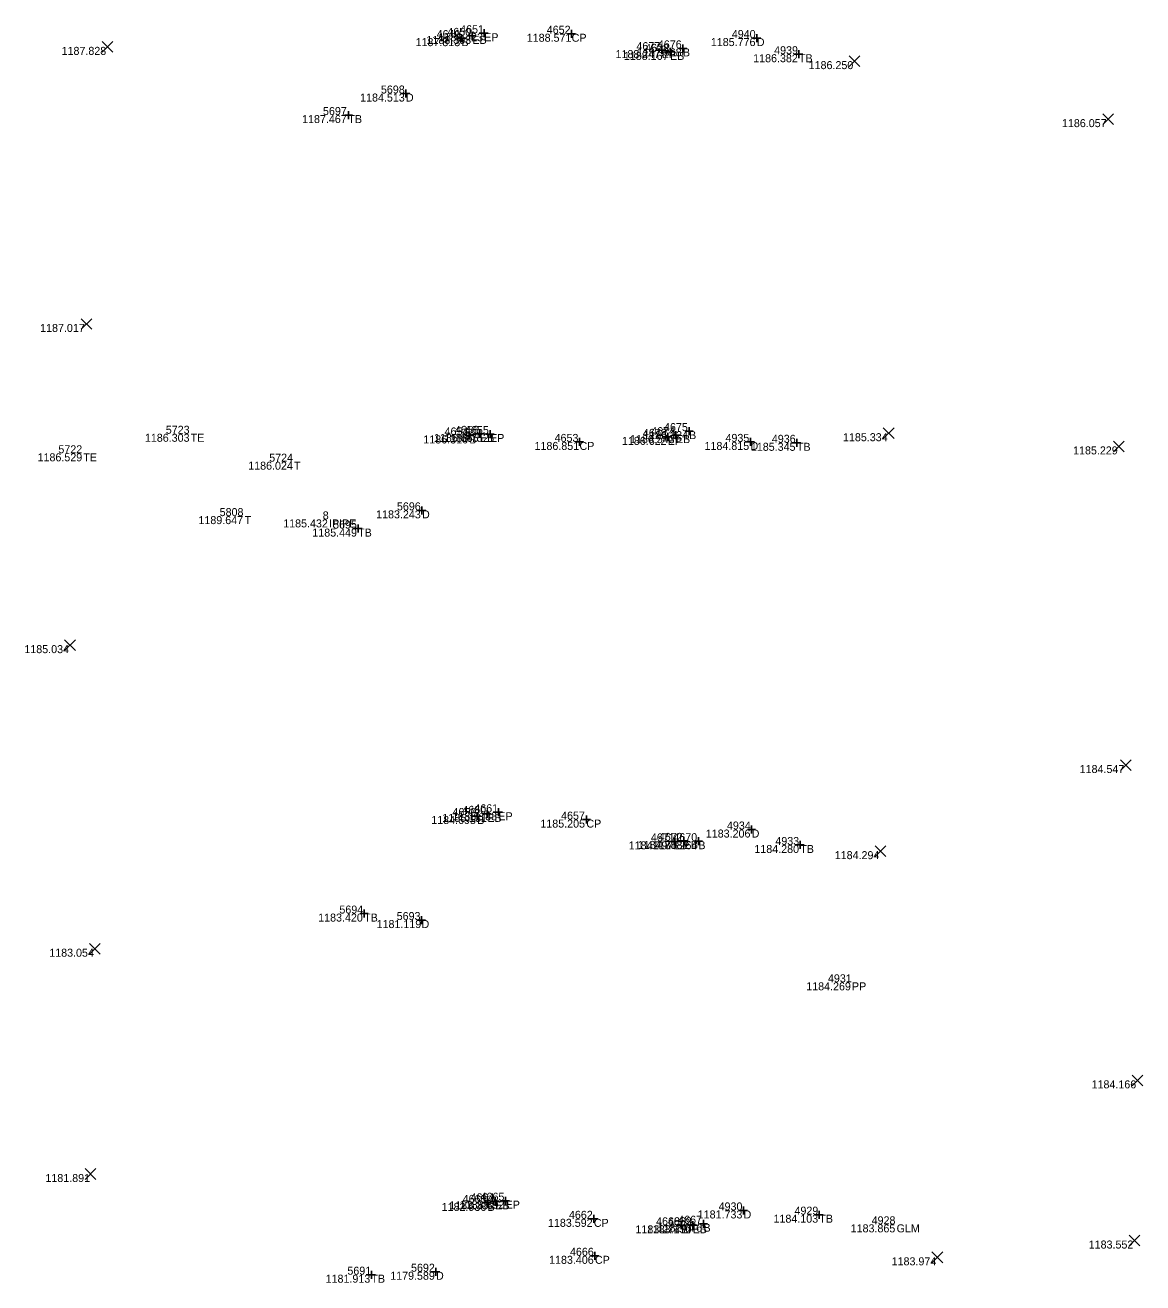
# Model space of a CAD drawing. Extents: x 2044997 to 2050342, y 455233 to 458054.
# Drawn here: x 2047582.6 to 2047722.3, y 455973.2 to 456130.3 of the extents above; entities that cross this region are included whole.
import ezdxf

# ---------------------------------------------------------------- set-up
doc = ezdxf.new("R2010")
doc.units = 0
for name, color, linetype in [('SV_X_Random_Point', 7, 'Continuous'), ('SV_X_Shot_Marker', 7, 'Continuous'), ('SV_X_Text_Comment', 7, 'Continuous'), ('SV_X_Text_Elevation', 7, 'Continuous'), ('SV_X_Text_Name', 7, 'Continuous')]:
    doc.layers.add(name, color=color, linetype=linetype)

msp = doc.modelspace()

# ---------------------------------------------------------------- linework, layer by layer
at = {"layer": 'SV_X_Random_Point'}
for p, q in [((2047592.23, 456126.95), (2047593.56, 456128.29)), ((2047592.23, 456128.29), (2047593.56, 456126.95)), ((2047685.57, 456125.17), (2047686.9, 456126.5)), ((2047685.57, 456126.5), (2047686.9, 456125.17)), ((2047717.26, 456117.92), (2047718.59, 456119.25)), ((2047717.26, 456119.25), (2047718.59, 456117.92)), ((2047589.59, 456092.33), (2047590.93, 456093.66)), ((2047589.59, 456093.66), (2047590.93, 456092.33)), ((2047689.83, 456078.68), (2047691.17, 456080.02)), ((2047689.83, 456080.02), (2047691.17, 456078.68)), ((2047718.59, 456077.04), (2047719.92, 456078.37)), ((2047718.59, 456078.37), (2047719.92, 456077.04)), ((2047587.54, 456052.21), (2047588.88, 456053.54)), ((2047587.54, 456053.54), (2047588.88, 456052.21)), ((2047719.47, 456037.22), (2047720.81, 456038.56)), ((2047719.47, 456038.56), (2047720.81, 456037.22)), ((2047688.8, 456026.46), (2047690.13, 456027.8)), ((2047688.8, 456027.8), (2047690.13, 456026.46)), ((2047590.66, 456014.27), (2047591.99, 456015.61)), ((2047590.66, 456015.61), (2047591.99, 456014.27)), ((2047720.92, 455997.82), (2047722.25, 455999.16)), ((2047720.92, 455999.16), (2047722.25, 455997.82)), ((2047590.09, 455986.12), (2047591.42, 455987.46)), ((2047590.09, 455987.46), (2047591.42, 455986.12)), ((2047720.55, 455977.81), (2047721.89, 455979.14)), ((2047720.55, 455979.14), (2047721.89, 455977.81)), ((2047695.91, 455975.71), (2047697.25, 455977.05)), ((2047695.91, 455977.05), (2047697.25, 455975.71))]:
    msp.add_line(p, q, dxfattribs=at)
at = {"layer": 'SV_X_Shot_Marker'}
for p, q in [((2047637.12, 456129.21), (2047637.12, 456128.21)), ((2047638.48, 456129.49), (2047638.48, 456128.49)), ((2047639.46, 456129.32), (2047640.46, 456129.32)), ((2047639.96, 456129.82), (2047639.96, 456128.82)), ((2047639.96, 456129.32), (2047639.96, 456129.32)), ((2047650.39, 456129.26), (2047651.39, 456129.26)), ((2047650.89, 456129.76), (2047650.89, 456128.76)), ((2047650.89, 456129.26), (2047650.89, 456129.26)), ((2047674.02, 456129.22), (2047674.02, 456128.22)), ((2047636.62, 456128.71), (2047637.62, 456128.71)), ((2047637.12, 456128.71), (2047637.12, 456128.71)), ((2047637.98, 456128.99), (2047638.98, 456128.99)), ((2047638.48, 456128.99), (2047638.48, 456128.99)), ((2047662.14, 456127.71), (2047662.14, 456126.71)), ((2047664.79, 456127.93), (2047664.79, 456126.93)), ((2047673.52, 456128.72), (2047674.52, 456128.72)), ((2047674.02, 456128.72), (2047674.02, 456128.72)), ((2047661.64, 456127.21), (2047662.64, 456127.21)), ((2047662.14, 456127.21), (2047662.14, 456127.21)), ((2047662.69, 456126.99), (2047663.69, 456126.99)), ((2047663.19, 456127.49), (2047663.19, 456126.49)), ((2047663.19, 456126.99), (2047663.19, 456126.99)), ((2047664.29, 456127.43), (2047665.29, 456127.43)), ((2047664.79, 456127.43), (2047664.79, 456127.43)), ((2047678.79, 456126.7), (2047679.79, 456126.7)), ((2047679.29, 456127.2), (2047679.29, 456126.2)), ((2047679.29, 456126.7), (2047679.29, 456126.7)), ((2047629.68, 456121.79), (2047630.68, 456121.79)), ((2047630.18, 456122.29), (2047630.18, 456121.29)), ((2047630.18, 456121.79), (2047630.18, 456121.79)), ((2047622.49, 456119.1), (2047623.49, 456119.1)), ((2047622.99, 456119.6), (2047622.99, 456118.6)), ((2047622.99, 456119.1), (2047622.99, 456119.1)), ((2047637.6, 456079.07), (2047638.6, 456079.07)), ((2047638.1, 456079.57), (2047638.1, 456078.57)), ((2047638.1, 456079.07), (2047638.1, 456079.07)), ((2047638.93, 456079.27), (2047639.93, 456079.27)), ((2047639.43, 456079.77), (2047639.43, 456078.77)), ((2047639.43, 456079.27), (2047639.43, 456079.27)), ((2047640.2, 456079.25), (2047641.2, 456079.25)), ((2047640.7, 456079.75), (2047640.7, 456078.75)), ((2047640.7, 456079.25), (2047640.7, 456079.25)), ((2047662.4, 456078.89), (2047663.4, 456078.89)), ((2047662.9, 456079.39), (2047662.9, 456078.39)), ((2047662.9, 456078.89), (2047662.9, 456078.89)), ((2047663.41, 456079.11), (2047664.41, 456079.11)), ((2047663.91, 456079.61), (2047663.91, 456078.61)), ((2047663.91, 456079.11), (2047663.91, 456079.11)), ((2047665.06, 456079.61), (2047666.06, 456079.61)), ((2047665.56, 456080.11), (2047665.56, 456079.11)), ((2047665.56, 456079.61), (2047665.56, 456079.61)), ((2047651.37, 456078.26), (2047652.37, 456078.26)), ((2047651.87, 456078.76), (2047651.87, 456077.76)), ((2047651.87, 456078.26), (2047651.87, 456078.26)), ((2047672.74, 456078.26), (2047673.74, 456078.26)), ((2047673.24, 456078.76), (2047673.24, 456077.76)), ((2047673.24, 456078.26), (2047673.24, 456078.26)), ((2047678.53, 456078.15), (2047679.53, 456078.15)), ((2047679.03, 456078.65), (2047679.03, 456077.65)), ((2047679.03, 456078.15), (2047679.03, 456078.15)), ((2047631.69, 456069.71), (2047632.69, 456069.71)), ((2047632.19, 456070.21), (2047632.19, 456069.21)), ((2047632.19, 456069.71), (2047632.19, 456069.71)), ((2047624.21, 456067.93), (2047624.21, 456066.93)), ((2047623.71, 456067.43), (2047624.71, 456067.43)), ((2047624.21, 456067.43), (2047624.21, 456067.43)), ((2047639.09, 456032.02), (2047639.09, 456031.02)), ((2047639.85, 456031.79), (2047640.85, 456031.79)), ((2047640.35, 456032.29), (2047640.35, 456031.29)), ((2047640.35, 456031.79), (2047640.35, 456031.79)), ((2047641.23, 456031.99), (2047642.23, 456031.99)), ((2047641.73, 456032.49), (2047641.73, 456031.49)), ((2047641.73, 456031.99), (2047641.73, 456031.99)), ((2047638.59, 456031.52), (2047639.59, 456031.52)), ((2047639.09, 456031.52), (2047639.09, 456031.52)), ((2047652.23, 456031.07), (2047653.23, 456031.07)), ((2047652.73, 456031.57), (2047652.73, 456030.57)), ((2047652.73, 456031.07), (2047652.73, 456031.07)), ((2047673.38, 456030.33), (2047673.38, 456029.33)), ((2047663.79, 456028.85), (2047663.79, 456027.85)), ((2047664.9, 456028.91), (2047664.9, 456027.91)), ((2047666.72, 456028.87), (2047666.72, 456027.87)), ((2047672.88, 456029.83), (2047673.88, 456029.83)), ((2047673.38, 456029.83), (2047673.38, 456029.83)), ((2047663.29, 456028.35), (2047664.29, 456028.35)), ((2047663.79, 456028.35), (2047663.79, 456028.35)), ((2047664.4, 456028.41), (2047665.4, 456028.41)), ((2047664.9, 456028.41), (2047664.9, 456028.41)), ((2047666.22, 456028.37), (2047667.22, 456028.37)), ((2047666.72, 456028.37), (2047666.72, 456028.37)), ((2047678.95, 456027.9), (2047679.95, 456027.9)), ((2047679.45, 456028.4), (2047679.45, 456027.4)), ((2047679.45, 456027.9), (2047679.45, 456027.9)), ((2047624.46, 456019.33), (2047625.46, 456019.33)), ((2047624.96, 456019.83), (2047624.96, 456018.83)), ((2047624.96, 456019.33), (2047624.96, 456019.33)), ((2047631.63, 456018.52), (2047632.63, 456018.52)), ((2047632.13, 456019.02), (2047632.13, 456018.02)), ((2047632.13, 456018.52), (2047632.13, 456018.52)), ((2047639.88, 455983.18), (2047640.88, 455983.18)), ((2047640.38, 455983.68), (2047640.38, 455982.68)), ((2047640.38, 455983.18), (2047640.38, 455983.18)), ((2047640.84, 455983.38), (2047641.84, 455983.38)), ((2047641.34, 455983.88), (2047641.34, 455982.88)), ((2047641.34, 455983.38), (2047641.34, 455983.38)), ((2047642.14, 455983.46), (2047643.14, 455983.46)), ((2047642.64, 455983.96), (2047642.64, 455982.96)), ((2047642.64, 455983.46), (2047642.64, 455983.46)), ((2047653.66, 455981.69), (2047653.66, 455980.69)), ((2047671.87, 455982.24), (2047672.87, 455982.24)), ((2047672.37, 455982.74), (2047672.37, 455981.74)), ((2047672.37, 455982.24), (2047672.37, 455982.24)), ((2047681.33, 455981.71), (2047682.33, 455981.71)), ((2047681.83, 455982.21), (2047681.83, 455981.21)), ((2047681.83, 455981.71), (2047681.83, 455981.71)), ((2047653.16, 455981.19), (2047654.16, 455981.19)), ((2047653.66, 455981.19), (2047653.66, 455981.19)), ((2047664.06, 455980.38), (2047665.06, 455980.38)), ((2047664.56, 455980.88), (2047664.56, 455979.88)), ((2047664.56, 455980.38), (2047664.56, 455980.38)), ((2047665.51, 455980.39), (2047666.51, 455980.39)), ((2047666.01, 455980.89), (2047666.01, 455979.89)), ((2047666.01, 455980.39), (2047666.01, 455980.39)), ((2047666.86, 455980.58), (2047667.86, 455980.58)), ((2047667.36, 455981.08), (2047667.36, 455980.08)), ((2047667.36, 455980.58), (2047667.36, 455980.58)), ((2047653.8, 455977.07), (2047653.8, 455976.07)), ((2047653.3, 455976.57), (2047654.3, 455976.57)), ((2047653.8, 455976.57), (2047653.8, 455976.57)), ((2047625.37, 455974.21), (2047626.37, 455974.21)), ((2047625.87, 455974.71), (2047625.87, 455973.71)), ((2047625.87, 455974.21), (2047625.87, 455974.21)), ((2047633.44, 455974.58), (2047634.44, 455974.58)), ((2047633.94, 455975.08), (2047633.94, 455974.08)), ((2047633.94, 455974.58), (2047633.94, 455974.58))]:
    msp.add_line(p, q, dxfattribs=at)

# ---------------------------------------------------------------- texts
at = {"layer": 'SV_X_Text_Comment'}
for s, p in [('EP', (2047639.96, 456128.32)), ('CP', (2047650.89, 456128.26)), ('B', (2047637.12, 456127.71)), ('EB', (2047638.48, 456127.99)), ('D', (2047674.02, 456127.72)), ('EP', (2047662.14, 456126.21)), ('EB', (2047663.19, 456125.99)), ('B', (2047664.79, 456126.43)), ('TB', (2047679.29, 456125.7)), ('D', (2047630.18, 456120.79)), ('TB', (2047622.99, 456118.1)), ('TE', (2047603.29, 456078.28)), ('B', (2047638.1, 456078.07)), ('EB', (2047639.43, 456078.27)), ('EP', (2047640.7, 456078.25)), ('EP', (2047662.9, 456077.89)), ('EB', (2047663.91, 456078.11)), ('B', (2047665.56, 456078.61)), ('CP', (2047651.87, 456077.26)), ('D', (2047673.24, 456077.26)), ('TB', (2047679.03, 456077.15)), ('TE', (2047589.87, 456075.84)), ('T', (2047616.19, 456074.79)), ('D', (2047632.19, 456068.71)), ('T', (2047610.03, 456067.99)), ('IPIPE', (2047620.58, 456067.58)), ('TB', (2047624.21, 456066.43)), ('EB', (2047640.35, 456030.79)), ('EP', (2047641.73, 456030.99)), ('B', (2047639.09, 456030.52)), ('CP', (2047652.73, 456030.07)), ('D', (2047673.38, 456028.83)), ('EP', (2047663.79, 456027.35)), ('EB', (2047664.9, 456027.41)), ('B', (2047666.72, 456027.37)), ('TB', (2047679.45, 456026.9)), ('TB', (2047624.96, 456018.33)), ('D', (2047632.13, 456017.52)), ('PP', (2047685.91, 456009.74)), ('B', (2047640.38, 455982.18)), ('EB', (2047641.34, 455982.38)), ('EP', (2047642.64, 455982.46)), ('D', (2047672.37, 455981.24)), ('TB', (2047681.83, 455980.71)), ('CP', (2047653.66, 455980.19)), ('EP', (2047664.56, 455979.38)), ('EB', (2047666.01, 455979.39)), ('B', (2047667.36, 455979.58)), ('GLM', (2047691.49, 455979.5)), ('CP', (2047653.8, 455975.57)), ('TB', (2047625.87, 455973.21)), ('D', (2047633.94, 455973.58))]:
    msp.add_text(s, height=1, dxfattribs=at).set_placement(p)
at = {"layer": 'SV_X_Text_Elevation'}
for s, p in [('1188.423', (2047634.24, 456128.32)), ('1188.571', (2047645.28, 456128.26)), ('1187.828', (2047587.16, 456126.62)), ('1187.813', (2047631.39, 456127.71)), ('1188.303', (2047632.75, 456127.99)), ('1185.776', (2047668.28, 456127.72)), ('1188.247', (2047656.37, 456126.21)), ('1188.167', (2047657.41, 456125.99)), ('1187.968', (2047659.05, 456126.43)), ('1186.382', (2047673.57, 456125.7)), ('1186.250', (2047680.5, 456124.84)), ('1184.513', (2047624.46, 456120.79)), ('1187.467', (2047617.21, 456118.1)), ('1186.057', (2047712.15, 456117.59)), ('1187.017', (2047584.48, 456092)), ('1186.303', (2047597.57, 456078.28)), ('1186.316', (2047632.36, 456078.07)), ('1186.665', (2047633.68, 456078.27)), ('1186.752', (2047634.97, 456078.25)), ('1186.622', (2047657.17, 456077.89)), ('1186.543', (2047658.18, 456078.11)), ('1186.324', (2047659.85, 456078.61)), ('1185.334', (2047684.79, 456078.35)), ('1186.851', (2047646.25, 456077.26)), ('1184.815', (2047667.49, 456077.26)), ('1185.345', (2047673.28, 456077.15)), ('1185.229', (2047713.54, 456076.7)), ('1186.529', (2047584.16, 456075.84)), ('1186.024', (2047610.48, 456074.79)), ('1183.243', (2047626.46, 456068.71)), ('1189.647', (2047604.26, 456067.99)), ('1185.432', (2047614.85, 456067.58)), ('1185.449', (2047618.49, 456066.43)), ('1185.034', (2047582.51, 456051.87)), ('1184.547', (2047714.36, 456036.89)), ('1185.131', (2047634.73, 456030.79)), ('1185.188', (2047635.99, 456030.99)), ('1184.695', (2047633.35, 456030.52)), ('1185.205', (2047646.98, 456030.07)), ('1183.206', (2047667.65, 456028.83)), ('1184.797', (2047658.02, 456027.35)), ('1184.738', (2047659.16, 456027.41)), ('1184.264', (2047661.02, 456027.37)), ('1184.280', (2047673.72, 456026.9)), ('1184.294', (2047683.76, 456026.13)), ('1183.420', (2047619.22, 456018.33)), ('1181.119', (2047626.52, 456017.52)), ('1183.054', (2047585.62, 456013.94)), ('1184.269', (2047680.2, 456009.74)), ('1184.166', (2047715.85, 455997.49)), ('1181.891', (2047585.14, 455985.79)), ('1182.936', (2047634.65, 455982.18)), ('1183.330', (2047635.6, 455982.38)), ('1183.392', (2047636.91, 455982.46)), ('1181.733', (2047666.64, 455981.24)), ('1184.103', (2047676.11, 455980.71)), ('1183.592', (2047647.93, 455980.19)), ('1183.274', (2047658.86, 455979.38)), ('1183.130', (2047660.28, 455979.39)), ('1182.676', (2047661.62, 455979.58)), ('1183.865', (2047685.75, 455979.5)), ('1183.552', (2047715.49, 455977.48)), ('1183.406', (2047648.07, 455975.57)), ('1183.974', (2047690.87, 455975.38)), ('1181.913', (2047620.15, 455973.21)), ('1179.589', (2047628.22, 455973.58))]:
    msp.add_text(s, height=1, dxfattribs=at).set_placement(p)
at = {"layer": 'SV_X_Text_Name'}
for s, p in [('4649', (2047634.02, 456128.71)), ('4650', (2047635.36, 456128.99)), ('4651', (2047636.96, 456129.32)), ('4652', (2047647.78, 456129.26)), ('4940', (2047670.9, 456128.72)), ('4677', (2047658.98, 456127.21)), ('4678', (2047660.07, 456126.99)), ('4676', (2047661.66, 456127.43)), ('4939', (2047676.19, 456126.7)), ('5698', (2047627.06, 456121.79)), ('5697', (2047619.82, 456119.1)), ('4675', (2047662.43, 456079.61)), ('5723', (2047600.18, 456079.28)), ('4654', (2047635.01, 456079.07)), ('4656', (2047636.3, 456079.27)), ('4655', (2047637.57, 456079.25)), ('4653', (2047648.76, 456078.26)), ('4673', (2047659.79, 456078.89)), ('4674', (2047660.82, 456079.11)), ('4935', (2047670.11, 456078.26)), ('4936', (2047675.9, 456078.15)), ('5722', (2047586.76, 456076.84)), ('5724', (2047613.1, 456075.79)), ('5808', (2047606.91, 456068.99)), ('8', (2047619.79, 456068.58)), ('5696', (2047629.06, 456069.71)), ('5695', (2047621.08, 456067.43)), ('4659', (2047635.99, 456031.52)), ('4660', (2047637.23, 456031.79)), ('4661', (2047638.73, 456031.99)), ('4657', (2047649.57, 456031.07)), ('4934', (2047670.29, 456029.83)), ('4671', (2047660.79, 456028.35)), ('4672', (2047661.78, 456028.41)), ('4670', (2047663.6, 456028.37)), ('4933', (2047676.34, 456027.9)), ('5694', (2047621.87, 456019.33)), ('5693', (2047629.03, 456018.52)), ('4931', (2047682.91, 456010.74)), ('4663', (2047637.27, 455983.18)), ('4664', (2047638.25, 455983.38)), ('4665', (2047639.51, 455983.46)), ('4930', (2047669.25, 455982.24)), ('4662', (2047650.55, 455981.19)), ('4667', (2047664.2, 455980.58)), ('4929', (2047678.73, 455981.71)), ('4928', (2047688.37, 455980.5)), ('4668', (2047661.44, 455980.38)), ('4669', (2047662.91, 455980.39)), ('4666', (2047650.68, 455976.57)), ('5691', (2047622.87, 455974.21)), ('5692', (2047630.82, 455974.58))]:
    msp.add_text(s, height=1, dxfattribs=at).set_placement(p)

doc.saveas('drawing.dxf')
